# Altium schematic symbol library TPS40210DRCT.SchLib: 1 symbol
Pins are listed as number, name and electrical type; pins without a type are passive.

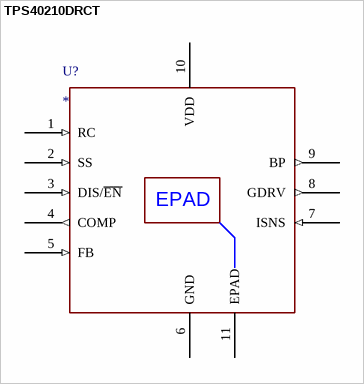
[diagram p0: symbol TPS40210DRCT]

## TPS40210DRCT
designator U?
GENERIC PART DESCRIPTION: 4.5-V TO 52-V INPUT CURRENT MODE BOOST CONTROLLER; ORDERABLE DEVICE NUMBER: TPS40210DRCT
footprint SON_DRC10_EP2P40X1P65 (Footprint not found)
pins: 1 RC (in), 2 SS (in), 3 DIS/~{EN} (in), 4 COMP (out), 5 FB (in), 6 GND (power), 7 ISNS (in), 8 GDRV (out), 9 BP (out), 10 VDD (power), 11 EPAD (power)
